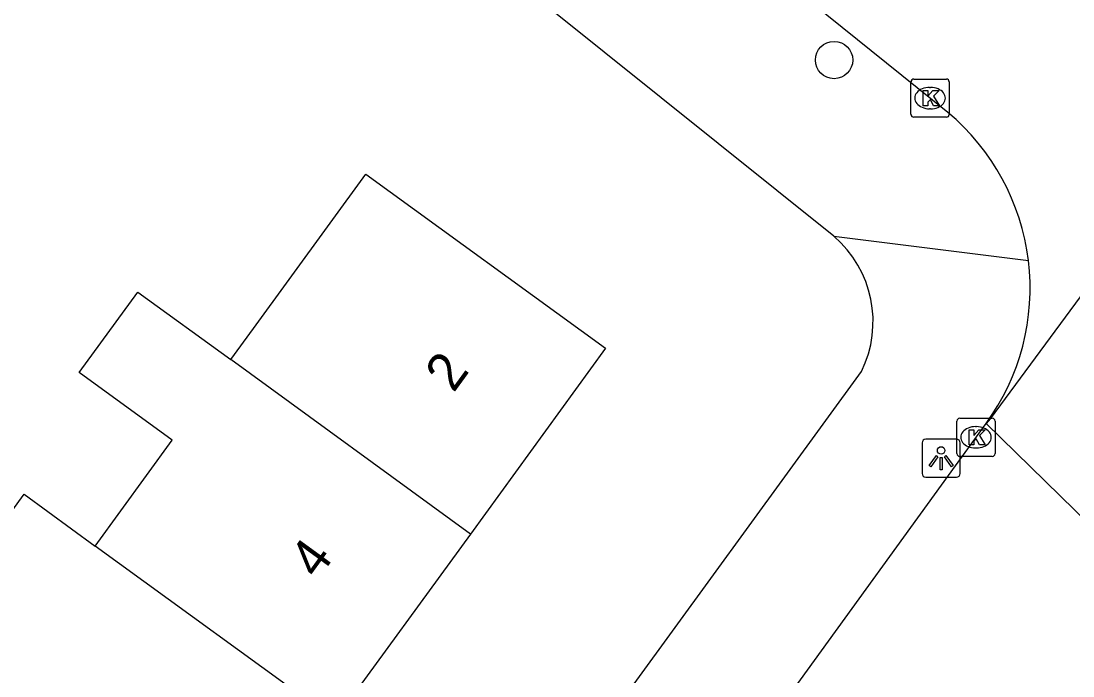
# Model space of a CAD drawing. Extents: x 159675 to 160530, y 382179 to 382901.
# Drawn here: x 160311.53 to 160339.08, y 382662.69 to 382679.85 of the extents above; entities that cross this region are included whole.
import ezdxf

# ---------------------------------------------------------------- set-up
doc = ezdxf.new("R2010")
doc.units = 0
for name, color, linetype in [('IMGEO_Boom', 7, 'Continuous'), ('IMGEO_Kolk', 7, 'Continuous'), ('IMGEO_Lichtpunt', 7, 'Continuous'), ('IMGEO_Pand', 7, 'Continuous'), ('IMGEO_Pand_nummerreeks', 7, 'Continuous'), ('IMGEO_Rijbaan_lokaal_gesloten', 7, 'Continuous'), ('IMGEO_Rijbaan_lokaal_open', 7, 'Continuous'), ('IMGEO_Voetpad_open', 7, 'Continuous')]:
    doc.layers.add(name, color=color, linetype=linetype)

msp = doc.modelspace()

# ---------------------------------------------------------------- linework, layer by layer
at = {"layer": 'IMGEO_Boom'}
msp.add_circle((160332.821, 382678.83), 0.489, dxfattribs=at)
at = {"layer": 'IMGEO_Kolk'}
for p, q in [((160334.836, 382677.406), (160334.836, 382678.258)), ((160334.911, 382678.332), (160335.763, 382678.332)), ((160335.837, 382678.258), (160335.837, 382677.406)), ((160335.324, 382678.112), (160335.349, 382678.112)), ((160335.763, 382677.332), (160334.911, 382677.332)), ((160335.347, 382677.552), (160335.322, 382677.552)), ((160336.038, 382668.519), (160336.038, 382669.371)), ((160336.113, 382669.445), (160336.965, 382669.445)), ((160337.039, 382669.371), (160337.039, 382668.519)), ((160336.526, 382669.225), (160336.551, 382669.225)), ((160336.549, 382668.665), (160336.524, 382668.665)), ((160336.965, 382668.445), (160336.113, 382668.445))]:
    msp.add_line(p, q, dxfattribs=at)
for points in [[(160334.836, 382677.406), (160334.836, 382678.258)], [(160334.911, 382678.332), (160335.763, 382678.332)], [(160335.837, 382678.258), (160335.837, 382677.406)], [(160335.157, 382678.032), (160335.28, 382678.032), (160335.28, 382677.881), (160335.41, 382678.032), (160335.574, 382678.032), (160335.428, 382677.881), (160335.581, 382677.632), (160335.429, 382677.632), (160335.344, 382677.796), (160335.28, 382677.729), (160335.28, 382677.632), (160335.157, 382677.632), (160335.157, 382678.032)], [(160335.763, 382677.332), (160334.911, 382677.332)], [(160336.038, 382668.519), (160336.038, 382669.371)], [(160336.113, 382669.445), (160336.965, 382669.445)], [(160337.039, 382669.371), (160337.039, 382668.519)], [(160336.359, 382669.145), (160336.482, 382669.145), (160336.482, 382668.994), (160336.612, 382669.145), (160336.776, 382669.145), (160336.63, 382668.994), (160336.783, 382668.745), (160336.631, 382668.745), (160336.546, 382668.909), (160336.482, 382668.842), (160336.482, 382668.745), (160336.359, 382668.745), (160336.359, 382669.145)], [(160336.965, 382668.445), (160336.113, 382668.445)]]:
    msp.add_lwpolyline(points, dxfattribs=at)
for centre, start, end in [((160334.913, 382678.256), 91.552, 178.448), ((160334.913, 382678.256), 91.552, 178.448), ((160335.761, 382678.256), 1.552, 88.448), ((160335.761, 382678.256), 1.552, 88.448), ((160334.913, 382677.408), 181.552, 268.448), ((160334.913, 382677.408), 181.552, 268.448), ((160335.761, 382677.408), 271.552, 358.448), ((160335.761, 382677.408), 271.552, 358.448), ((160336.115, 382669.369), 91.552, 178.448), ((160336.115, 382669.369), 91.552, 178.448), ((160336.963, 382669.369), 1.552, 88.448), ((160336.963, 382669.369), 1.552, 88.448), ((160336.115, 382668.521), 181.552, 268.448), ((160336.115, 382668.521), 181.552, 268.448), ((160336.963, 382668.521), 271.552, 358.448), ((160336.963, 382668.521), 271.552, 358.448)]:
    msp.add_arc(centre, 0.0765, start, end, dxfattribs=at)
for centre, major_axis, ratio, start_param, end_param in [((160335.323, 382677.832), (-0.387, 0.002), 0.722429, 4.712389, 7.853982), ((160335.348, 382677.832), (-0.39, 0.002), 0.717154, 1.570796, 4.712389), ((160336.525, 382668.945), (-0.387, 0.002), 0.722429, 4.712389, 7.853982), ((160336.55, 382668.945), (-0.39, 0.002), 0.717154, 1.570796, 4.712389)]:
    msp.add_ellipse(centre, major_axis=major_axis, ratio=ratio, start_param=start_param, end_param=end_param, dxfattribs=at)
at = {"layer": 'IMGEO_Lichtpunt'}
for p, q in [((160335.127, 382668.802), (160335.127, 382667.995)), ((160335.127, 382668.802), (160335.127, 382667.995)), ((160336.029, 382668.897), (160335.221, 382668.897)), ((160336.029, 382668.897), (160335.221, 382668.897)), ((160336.123, 382667.995), (160336.123, 382668.802)), ((160336.123, 382667.995), (160336.123, 382668.802)), ((160335.221, 382667.901), (160336.029, 382667.901)), ((160335.221, 382667.901), (160336.029, 382667.901))]:
    msp.add_line(p, q, dxfattribs=at)
for points in [[(160335.501, 382668.466), (160335.54, 382668.438), (160335.352, 382668.176), (160335.314, 382668.203), (160335.501, 382668.466)], [(160335.603, 382668.418), (160335.65, 382668.418), (160335.65, 382668.096), (160335.603, 382668.096), (160335.603, 382668.418)], [(160335.713, 382668.438), (160335.751, 382668.465), (160335.938, 382668.203), (160335.899, 382668.175), (160335.713, 382668.438)]]:
    msp.add_lwpolyline(points, dxfattribs=at)
msp.add_circle((160335.626, 382668.6), 0.0994, dxfattribs=at)
for centre, start, end in [((160335.221, 382668.802), 90, 180), ((160335.221, 382668.802), 90, 180), ((160336.029, 382668.802), 0, 90), ((160336.029, 382668.802), 0, 90), ((160335.221, 382667.995), 180, 270), ((160335.221, 382667.995), 180, 270), ((160336.029, 382667.995), 270, 0), ((160336.029, 382667.995), 270, 360)]:
    msp.add_arc(centre, 0.0946, start, end, dxfattribs=at)
at = {"layer": 'IMGEO_Pand'}
for points in [[(160317.019, 382670.98), (160317.614, 382671.798), (160320.554, 382675.842), (160326.832, 382671.278), (160323.294, 382666.411)], [(160313.468, 382666.096), (160315.484, 382668.869), (160313.049, 382670.642), (160314.585, 382672.752), (160317.019, 382670.98)], [(160323.294, 382666.411), (160317.019, 382670.98)], [(160309.935, 382661.236), (160308.069, 382662.592), (160311.603, 382667.452), (160313.468, 382666.096)], [(160323.294, 382666.411), (160319.746, 382661.531)], [(160319.746, 382661.531), (160313.468, 382666.096)]]:
    msp.add_lwpolyline(points, dxfattribs=at)
at = {"layer": 'IMGEO_Rijbaan_lokaal_gesloten'}
for points in [[(160344.376, 382679.555), (160336.907, 382669.427), (160336.801, 382669.305)], [(160304.717, 382625.008), (160315.311, 382639.622), (160336.801, 382669.305)], [(160336.801, 382669.305), (160342.623, 382663.625)]]:
    msp.add_lwpolyline(points, dxfattribs=at)
at = {"layer": 'IMGEO_Rijbaan_lokaal_open'}
msp.add_lwpolyline([(160335.801, 382677.459), (160327.048, 382684.5)], dxfattribs=at)
for centre, radius, start, end in [((160331.943, 382672.847), 6.013, 6.9913, 50.0847), ((160331.95, 382672.846), 6.006, 323.8715, 7.0112)]:
    msp.add_arc(centre, radius, start, end, dxfattribs=at)
at = {"layer": 'IMGEO_Voetpad_open'}
for points in [[(160332.815, 382674.214), (160316.257, 382687.487)], [(160332.815, 382674.214), (160337.911, 382673.579)], [(160303.037, 382628.76), (160333.537, 382670.671)]]:
    msp.add_lwpolyline(points, dxfattribs=at)
msp.add_arc((160330.899, 382671.978), 2.944, 333.637, 49.3993, dxfattribs=at)

# ---------------------------------------------------------------- texts
at = {"layer": 'IMGEO_Pand_nummerreeks'}
for s, p in [('2', (160322.853, 382670.09)), ('4', (160319.298, 382665.199))]:
    msp.add_text(s, height=1, rotation=53.9812, dxfattribs=at).set_placement(p)

doc.saveas('drawing.dxf')
